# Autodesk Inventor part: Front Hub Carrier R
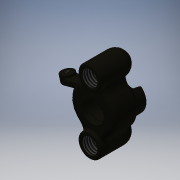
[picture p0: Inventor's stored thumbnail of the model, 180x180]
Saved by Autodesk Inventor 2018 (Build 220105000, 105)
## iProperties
Shininess: 4.0
Length Units: 11272
Angle Units: 11279
Time Units: 11290
Mass Units: 11286
Length Display Precision: 3
Angle Display Precision: 2
Compacted: True
Company: Autodesk
Created: 2001-01
Part Number: Front Hub Carrier R
Document SubType Name: Modeling
Designer: Autodesk, Inc.
Project: Inventor Samples
User Status: IN PROGRESS
Density: 1.28 g/cm^3
Mass: 9.6969 g
Surface Area: 49.8526 cm^2
Volume: 7.5757 cm^3
Material: Stiffzel
Appearance: Stiffzel
Density: 0.0
Volumn: 0.0
Area: 0.0
PropertySet Name: Model Information
Control State: 0
Master: False
Checked Out: False
Last Check In Date: 2002-04-10
Last Check In By: Kevin.s
Author: Autodesk, Inc.
Revision Number: A
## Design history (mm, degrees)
derived "Front Hub Carrier L.ipt"
body "Solid1"
tag "TaggingFeature2"
feature "Solid1::Front Hub Carrier L.ipt" dims "d9" = 10
